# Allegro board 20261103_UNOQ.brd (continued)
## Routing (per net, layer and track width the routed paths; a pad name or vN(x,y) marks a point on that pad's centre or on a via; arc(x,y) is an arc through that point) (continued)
SM_LNBBCLK1: length 19.4
  TOP w0.05: 28.97,28.33 28.97,28.88 SOC1.U29
  TOP w0.066: R702.1 29.7,13.66 27.27,13.66 26.18,14.75 26.18,21.86 28.96,24.64 28.96,28.33 28.97,28.33
SM_RESIN_N: length 28.1
  TOP w0.066: R1201.1 23,24.67 22.93,24.6 22.93,20.41 22.45,19.93 22.45,18.9 23.95,17.4 23.95,15.34 24.4,14.89 v3(24.4,13.41)
  S3 w0.064: v3(24.4,13.41) 24.6,13.61 28.29,13.61 29.67,14.99 v3(30.05,14.99) 30.1,15.04 30.1,15.81 30.88,16.59 36.09,16.59 36.66,16.02 37.13,16.02 37.45,15.7 v3(37.85,15.7)
SM_RESIN_N_R: length 9.5
  TOP w0.066: SOC1.AJ20 24,32.48 23.67,32.81 22.84,32.81 22.46,32.43 22.46,27.85 23.34,26.97 23.34,26.4 C1201.1 R1201.2
SM_THERM: length 6.8
  S3 w0.064: v3(38.97,15.13) 38.97,15.33 39.08,15.43 39.49,15.43 40.16,14.76 40.16,14.41 40.05,14.3 40.05,14.13 41.96,12.22 v3(41.96,10.54)
SOC_BID0: length 2.8
  TOP w0.066: SOC1.AH3 23.97,39.28 23.51,39.74 22.87,39.74 R1316.1 R1315.2
SOC_BID1: length 2.5
  TOP w0.066: SOC1.AJ2 23.94,39.68 23.3,40.32 22.89,40.32 R1318.1 R1317.2
SOC_BT_UART_CTS: length 46.2
  TOP w0.064: v3(23.77,61.87) 23.75,61.85 20.84,61.85 20.3,61.31 11.51,61.31 10.2,60 7.61,60 7.27,60.34 4.71,60.34 R2906.1
  S3 w0.064: v3(23.77,61.87) 23.89,61.75 23.89,57.59 24.91,56.57 24.91,51.65 34.04,42.52 34.04,40.4
  S3 w0.066: 34.04,40.4 33.87,40.23 33.87,40.18 v3(33.77,40.08)
SOC_BT_UART_RTS: length 45.2
  TOP w0.066: v3(33.78,40.5) 33.57,40.5 33.37,40.3 33.37,40.08 SOC1.F1
  S3 w0.064: v3(4.12,63.34) 4.52,62.94 7.34,62.94 8.44,61.84 v4(8.44,60.12) ; 33.89,40.62 33.89,42.44 24.75,51.58 24.75,55.97 v4(24.28,56.44)
  S3 w0.066: 33.89,40.62 v3(33.78,40.5)
  V5 w0.064: v4(8.44,60.12) 9.67,58.89 10.14,58.89 12.31,56.72 21.57,56.72 22.46,55.83 23.67,55.83 v4(24.28,56.44)
SOC_BT_UART_RX: length 33.3
  TOP w0.064: v3(22.69,60.46) 22.71,60.48 24.38,60.48 25.02,61.11 25.02,61.95 24.42,62.55 R2901.1
  S3 w0.064: v3(32.51,40.02) 32.51,41.58 27.73,46.36 26.36,46.36 25.73,46.99 22.97,46.99 21.22,48.74 21.22,52.93 20.74,53.41 20.74,57.62 22.69,59.57 v3(22.69,60.46)
SOC_BT_UART_TX: length 24.4
  TOP w0.064: v3(24.11,55.3) 24.43,55.62 24.43,58.29 R2908.1 ; 32.97,40.35 32.97,40.08 SOC1.G1
  TOP w0.066: v3(33.12,41.26) 32.97,41.11 32.97,40.35
  S3 w0.064: v3(24.11,55.3) 24.52,54.89 24.52,49.48 26.43,47.57 27.36,47.57 31.09,43.84 31.09,43.69 33.12,41.66 v3(33.12,41.26)
SOC_CAM_MCLK0: length 29.4
  TOP w0.05: v3(31.3,39.58) 31.3,39.61 31.37,39.68
  TOP w0.066: v3(26.58,44.88) v3(26.58,56.42)
  S3 w0.05: 31.46,40.44 31.46,39.93 31.3,39.77 v3(31.3,39.58)
  S3 w0.064: v3(26.58,44.88) 27.92,44.88 31.46,41.34 31.46,40.44 ; v3(26.58,56.42) v4(26.58,64.25)
  S6 w0.064: v4(26.58,64.25) v1(26.93,64.25)
  BOTTOM w0.066: R2638.1 27.08,64.25 v1(26.93,64.25)
SOC_CAM_MCLK0_R: length 13.1
  BOTTOM w0.066: R2638.2 D26046.2 29.37,63.4 30.22,64.25 35.46,64.25 36.2,63.52 JMEDIA1.16
SOC_CAM_MCLK1: length 52
  TOP w0.066: SOC1.M2 31,39.68 31.26,39.95 31.26,41 30.49,41.77 22.14,41.77 v3(21.41,41.05) ; v3(22.9,49.03) 22.65,48.78 15.31,48.78 v3(15.04,48.51)
  S3 w0.064: v3(21.41,41.05) 21.41,41.18 20.17,42.42 18.43,42.42 15.5,45.35 15.5,47.52 15.04,47.98 v3(15.04,48.51) ; v4(24.31,63.81) 23.24,62.74 23.24,59.17 21.26,57.19 21.26,53.68 23.08,51.86 23.08,49.21 v3(22.9,49.03)
  S6 w0.064: v1(24.56,63.69) 24.43,63.69 v4(24.31,63.81)
  BOTTOM w0.066: R2639.1 27.87,62.89 27.14,63.62 24.63,63.62 v1(24.56,63.69)
SOC_CAM_MCLK1_R: length 13.2
  BOTTOM w0.066: R2639.2 D26047.2 29.2,62.89 30.31,64 35.34,64 35.94,63.4 35.94,60.4 34.92,59.38 34.92,58.85
SOC_GPIO18: length 91.6
  TOP w0.066: SOC1.M1 30.97,40.08 30.97,40.6 30.38,41.19 22.25,41.19 21.79,40.73 v3(21.79,40.44)
  S3 w0.064: v3(21.79,40.44) 21.06,40.44 v4(20.9,40.6)
  V5 w0.064: v4(0.97,41.78) 0.75,41.55 0.75,4.56 1.82,3.49 4.28,3.49 4.44,3.65 v4(5.58,3.65)
  S6 w0.064: v4(20.9,40.6) 20.89,40.61 20.75,40.61 v1(20.62,40.74) ; v4(5.58,3.65) 6.43,4.5 8.78,4.5 10.78,2.5 13.32,2.5 v1(13.48,2.67) ; v4(0.97,41.78) 1.18,41.99 v1(1.19,41.99)
  BOTTOM w0.066: v1(13.48,2.67) 14.81,3.99 D26075.2 14.81,7.87 JMISC1.49 ; v1(1.19,41.99) 7.82,41.99 10.34,39.47 10.77,39.47 11.66,38.58 14.04,38.58 15.83,40.37 18.55,40.37 18.88,40.7 20.58,40.7 v1(20.62,40.74)
SOC_GPIO28: length 96.7
  TOP w0.066: v3(13.95,47.35) 13.13,47.35 12.34,48.14 6.06,48.14 5.79,47.87 3.81,47.87 3.28,48.4 1.42,48.4 1.19,48.17 1.19,4.61 1.93,3.87 3.23,3.87 4.1,4.74 v6(4.42,4.74)
  S3 w0.05: 31.62,40.44 31.62,39.92 31.49,39.8 31.49,39.77 31.48,39.76 31.48,39.4 v3(30.97,38.88)
  S3 w0.064: 31.62,40.44 31.62,41.45 27.81,45.26 26.19,45.26 25.91,44.98 22.99,44.98 v4(22.05,45.92) ; v4(14.28,47.35) v3(13.95,47.35)
  S6 w0.064: v4(14.28,47.35) 14.41,47.35 15.57,46.19 17.57,46.19 18.22,45.54 21.66,45.54 v4(22.05,45.92)
  G7 w0.064: v1(13.15,5.33) 12.83,5.65 5.61,5.65 4.7,4.74 v6(4.42,4.74)
  BOTTOM w0.066: JMISC1.51 13.49,7.93 D26076.2 13.49,5.67 v1(13.15,5.33)
SOC_GPIO_0_SE0: length 39.5
  S3 w0.05: 29.15,28.33 29.31,28.49 ; 29.58,29.47 v3(29.37,29.68)
  S3 w0.064: 29.58,29.47 29.58,28.87 29.55,28.84 29.55,28.81 29.44,28.7 29.41,28.7 29.31,28.6 29.31,28.49 ; 29.15,28.33 26.77,25.95 23.18,25.95 22.28,25.04 18.4,25.04 16.69,23.33 16.69,17.17 15.46,15.95 v4(14.38,15.95)
  S6 w0.064: v4(14.38,15.95) 14.38,14.88 21.62,7.64 21.62,6.5 v1(21.67,6.45)
  BOTTOM w0.066: JMISC1.37 22.22,7 v1(21.67,6.45)
SOC_GPIO_1_SE0: length 39.4
  S3 w0.05: v3(29.37,29.28) 29.17,29.08 29.17,28.54 28.96,28.33 28.87,28.33
  S3 w0.064: v4(13.84,15.98) 14.15,16.28 15.57,16.28 16.53,17.25 16.53,23.44 18.29,25.2 22.21,25.2 23.11,26.1 26.63,26.1 28.87,28.33
  S6 w0.064: v1(20.73,6.46) 21.09,6.82 21.09,7.95 13.84,15.2 v4(13.84,15.98)
  BOTTOM w0.066: JMISC1.39 20.95,7.01 20.73,6.79 v1(20.73,6.46)
SOC_GPIO_2_SE0: length 40.5
  S3 w0.05: 28.61,28.33 28.79,28.51 28.79,29.5 v3(28.97,29.68)
  S3 w0.064: 28.61,28.33 26.53,26.25 23.01,26.25 22.13,25.37 18.2,25.37 16.35,23.52 16.35,17.3 15.49,16.43 13.77,16.43 v4(13.31,15.98)
  S6 w0.064: v1(19.84,6.46) 20.24,6.46 20.8,7.02 20.8,8.02 13.31,15.51 v4(13.31,15.98)
  BOTTOM w0.066: JMISC1.41 19.84,7.93 v1(19.84,6.46)
SOC_GPIO_3_SE0: length 40.2
  S3 w0.05: 28.19,28.33 28.39,28.53 28.39,29.5 v3(28.57,29.68)
  S3 w0.064: v4(12.85,16.43) 13.18,16.76 15.38,16.76 16.07,17.45 16.07,23.72 18.03,25.68 22.03,25.68 22.91,26.55 26.41,26.55 28.19,28.33
  S6 w0.064: v1(18.62,6.46) 18.62,6.98 19.44,7.8 19.44,9.16 12.85,15.75 v4(12.85,16.43)
  BOTTOM w0.066: JMISC1.43 18.41,6.67 v1(18.62,6.46)
SOC_GPIO_82_SE0: length 41.4
  S3 w0.05: 28.39,28.33 28.57,28.51 v3(28.57,29.28)
  S3 w0.064: 28.39,28.33 26.46,26.4 22.96,26.4 22.09,25.53 18.11,25.53 16.22,23.64 16.22,17.38 15.44,16.61 13.49,16.61 12.9,16.03 12.29,16.03 v4(12.22,15.95)
  S6 w0.064: v1(17.32,6.48) 17.32,6.62 18.34,7.64 18.34,9.12 12.32,15.14 12.32,15.85 v4(12.22,15.95)
  BOTTOM w0.066: JMISC1.47 16.06,7.9 D26074.2 17.28,6.44 v1(17.32,6.48)
SOC_GPIO_86_SE0: length 36.9
  TOP w0.05: 28.57,28.33 SOC1.V30
  TOP w0.066: v3(25.73,16.41) 25.73,17.53 25.77,17.57 25.77,22.18 28.57,24.97 28.57,28.33
  S3 w0.064: v3(25.73,16.41) 21.59,16.41 18.82,13.64 v4(14.36,13.64)
  S6 w0.064: v4(14.36,13.64) 14.48,13.64 18.48,9.64 18.48,7.56 17.71,6.79 v1(17.71,6.48)
  BOTTOM w0.066: v1(17.71,6.48) 17.71,6.94 17.14,7.5 JMISC1.45
SOC_GPIO_98: length 85.6
  TOP w0.066: v6(4.25,6.35) 4.17,6.43 1.81,6.43 1.34,6.9 1.34,38.99 1.64,39.29 3.24,39.29 3.61,38.92 v3(6.88,38.92)
  G2 w0.064: v3(25.39,30.88) 24.99,31.28 v2(24.97,31.28)
  S3 w0.064: v3(6.88,38.92) 6.88,38.55 8.73,36.7 10.2,36.7 13.6,33.29 19.11,33.29 22.31,30.09 24.6,30.09 v3(25.39,30.88)
  G7 w0.064: v1(17.63,10.91) 18.3,10.24 18.3,7.82 16.55,6.07 4.53,6.07 v6(4.25,6.35)
  BOTTOM w0.066: D26091.2 17.16,13.46 17.16,12 17.14,11.98 17.14,11.4 v1(17.63,10.91)
SOC_GPIO_99: length 78.9
  TOP w0.066: v6(4.22,6.91) 3.75,7.38 3.75,8.87 3.84,8.96 3.84,37.98 4.52,38.66 6.97,38.66 7.27,38.36 v3(7.49,38.36)
  G2 w0.064: v2(24.57,31.28) v3(24.57,30.84)
  S3 w0.064: v3(7.49,38.36) 7.49,38.15 8.8,36.85 10.26,36.85 13.66,33.44 19.17,33.44 22.37,30.24 24.07,30.24 24.57,30.74 v3(24.57,30.84)
  G7 w0.064: v1(17.3,10.83) 18.14,9.99 18.14,7.89 16.44,6.19 5.05,6.19 4.33,6.91 v6(4.22,6.91)
  BOTTOM w0.066: D26092.2 15.69,13.62 15.87,13.44 15.87,11.24 16.16,10.95 17.18,10.95 v1(17.3,10.83)
SOC_GPIO_100: length 77.4
  TOP w0.066: v3(7.84,38.12) 7.22,38.12 6.92,38.42 4.63,38.42 3.98,37.77 3.98,8.85 3.9,8.77 3.9,7.9 v6(4.25,7.55)
  G2 w0.064: v2(24.17,31.28) v3(24.17,30.85)
  S3 w0.064: v3(7.84,38.12) 8.92,37.04 10.29,37.04 13.73,33.6 19.21,33.6 22.43,30.38 23.98,30.38 24.17,30.57 v3(24.17,30.85)
  G7 w0.064: v1(16.94,10.65) 17.24,10.35 17.24,7.17 16.39,6.32 5.48,6.32 v6(4.25,7.55)
  BOTTOM w0.066: D26093.2 14.42,13.62 14.6,13.44 14.6,11.42 15.24,10.78 16.81,10.78 v1(16.94,10.65)
SOC_GPIO_101: length 79.6
  TOP w0.066: v6(4.24,8.27) 4.12,8.39 4.12,37.4 4.85,38.13 v3(6.86,38.13)
  G2 w0.064: v2(25.77,31.68) v3(25.77,31.3)
  S3 w0.064: v3(25.77,31.3) 25.77,30.87 24.82,29.92 22.24,29.92 19.04,33.12 13.53,33.12 10.22,36.43 8.56,36.43 v3(6.86,38.13)
  G7 w0.064: v6(4.24,8.27) 4.77,7.74 4.77,7.28 5.59,6.46 16.33,6.46 17.1,7.23 17.1,10.02 v1(16.86,10.26)
  BOTTOM w0.066: v1(16.86,10.26) 16.53,10.59 13.73,10.59 13.33,10.99 13.33,13.44 13.15,13.62 D26094.2
SOC_I2S_D0: length 29.6
  TOP w0.064: v3(21.22,35.88) 21.22,36 20.13,37.09 20.13,41.67 21.41,42.95 36.42,42.95 36.55,43.09
  S3 w0.064: v3(21.22,35.88) 21.25,35.85 21.6,35.85 22.6,34.85 22.6,32.09 22.79,31.9 23.01,31.9 23.22,31.68 v3(24.17,31.68)
SOC_I2S_D0_R: length 9.8
  G2 w0.064: v3(36.37,51.69) 36.37,51.74 v2(36.53,51.89)
  S3 w0.064: v3(36.37,51.69) 36.37,51.41 36.02,51.05 35.46,51.05 35.1,50.7 35.1,46.81 36.55,45.36 v3(36.55,43.6)
SOC_I2S_SCK: length 31.7
  TOP w0.064: v3(21.51,35.18) 21.32,35.37 21.32,35.67 21.43,35.78 21.43,35.99 20.31,37.11 20.31,41.6 21.49,42.78 37,42.78 R3016.1
  S3 w0.064: v3(25.37,31.68) 25.16,31.47 24.62,31.47 24.39,31.25 23.24,31.25 22.97,31.52 22.67,31.52 22.21,31.98 22.21,34.73 21.76,35.18 v3(21.51,35.18)
SOC_I2S_SCK_R: length 10.4
  S3 w0.064: v3(37,51.97) 36.58,51.54 36.58,51.16 36.25,50.83 35.61,50.83 35.27,50.48 35.27,46.87 36.71,45.43 36.71,43.85 v3(37.14,43.42)
SOC_I2S_WS: length 30.8
  TOP w0.064: R3017.1 37.6,42.6 21.56,42.6 20.48,41.52 20.48,37.19 21.61,36.06 21.61,35.65 v3(21.53,35.57)
  S3 w0.064: v3(24.57,31.68) 24.33,31.44 23.25,31.44 22.98,31.71 22.72,31.71 22.39,32.04 22.39,34.85 21.65,35.59 21.55,35.59 v3(21.53,35.57)
SOC_I2S_WS_R: length 10.3
  S3 w0.064: v3(37.79,43.3) 36.89,44.19 36.89,45.51 35.45,46.95 35.45,50.39 35.71,50.65 36.42,50.65 36.97,51.2 v3(36.97,51.54)
SOC_LED1_BLU: length 54.7
  TOP w0.066: v3(22.11,40.66) 22.39,40.93 24.57,40.93 25.77,39.73 SOC1.AE2 ; v3(19.06,41.66) 19.06,41.75 20.95,43.64 28.81,43.64 30.1,44.93 38.95,44.93 40.41,43.47 45.36,43.47 45.76,43.07 v3(46.84,43.07)
  S3 w0.064: v3(22.11,40.66) 21.25,40.66 20.25,41.66 v3(19.06,41.66) ; v4(46.78,43.36) 46.84,43.3 v3(46.84,43.07)
  S6 w0.064: v1(47.05,43.26) 46.95,43.36 v4(46.78,43.36)
  BOTTOM w0.066: v1(47.05,43.26) 47.05,43.26 48.68,41.63 48.68,35.1 47.96,34.38 41.58,34.38 R2714.1
SOC_LED1_BLU_B: length 1.5
  BOTTOM w0.066: Q2708.2 40.85,33.9 C2703.1 R2714.2
SOC_LED1_BLU_C: length 42.3
  BOTTOM w0.066: R2725.2 41.95,6.22 42.73,7 48.28,7 48.76,7.48 48.76,22.98 43.15,28.59 39.48,28.59 37.7,30.37 37.7,32.6 37.4,32.9 37.4,34.3 37.65,34.55 Q2708.6
SOC_LED1_BLU_D: length 3.8
  TOP w0.066: v3(41.91,4.44) 42,4.53 44.17,4.53 44.49,4.21 D27301.3
  S3 w0.064: v3(41.91,4.44) 41.79,4.44 v4(41.61,4.62)
  S6 w0.064: v1(41.95,4.85) 41.84,4.85 v4(41.61,4.62)
SOC_LED1_GRN: length 54.7
  TOP w0.066: v3(47.8,43.64) 47.7,43.54 45.73,43.54 45.49,43.78 40.54,43.78 39.08,45.24 29.97,45.24 28.68,43.95 20.74,43.95 18.69,41.9 18.69,39.3 v3(18.81,39.18)
  S3 w0.064: v3(47.8,43.64) 47.94,43.64 48.1,43.8 v4(48.1,43.82) ; v3(18.81,39.18) 18.89,39.1 24.02,39.1 24.2,39.28 v3(25.37,39.28)
  S6 w0.064: v4(48.1,43.82) v1(48.1,43.52)
  BOTTOM w0.066: v1(48.1,43.52) 48.08,43.5 48.08,43.29 49.26,42.11 49.26,34.86 48.2,33.8 46.05,33.8 R2713.1
SOC_LED1_GRN_B: length 3
  BOTTOM w0.066: Q2707.5 44.3,31.9 44.1,32.1 44.1,32.9 44.55,33.35 C2702.1 R2713.2
SOC_LED1_GRN_C: length 34.2
  BOTTOM w0.066: Q2707.3 43.65,32.55 43.9,32.3 43.9,31.04 44.27,30.67 46.83,30.67 49.34,28.16 49.34,7.21 48.41,6.28 45.8,6.28 45.64,6.12 R2724.2
SOC_LED1_GRN_D: length 2.6
  TOP w0.066: D27301.4 44.51,3.13 v3(44.51,3.52)
  S3 w0.064: v4(44.85,3.61) 44.76,3.52 v3(44.51,3.52)
  S6 w0.064: v4(44.85,3.61) v1(45.27,3.61)
  BOTTOM w0.066: v1(45.27,3.61) 45.64,3.98 R2724.1
SOC_LED1_RED: length 57
  TOP w0.066: v3(47.26,43.31) 45.75,43.31 45.43,43.63 40.48,43.63 39.02,45.09 30.03,45.09 28.74,43.8 20.8,43.8 18.84,41.84 18.84,39.54 v3(19.03,39.35)
  S3 w0.064: v3(19.03,39.35) 19.14,39.24 23.92,39.24 24.13,39.45 24.73,39.45 v3(24.97,39.68) ; v3(47.26,43.31) 47.61,43.31 v4(47.65,43.27)
  S6 w0.064: v4(47.65,43.27) 47.65,43.46 v1(47.81,43.62)
  BOTTOM w0.066: v1(47.81,43.62) 47.81,43.35 49.11,42.05 49.11,34.92 48.14,33.95 43.65,33.95 42.75,33.05 R2712.1
SOC_LED1_RED_B: length 1.5
  BOTTOM w0.066: R2712.2 C2701.1 43.05,31.95 Q2707.2
SOC_LED1_RED_C: length 30.4
  BOTTOM w0.066: R2723.2 48.16,5.82 49.49,7.15 49.49,28.3 46.95,30.84 45.83,30.84 45.41,31.25 Q2707.6
SOC_LED1_RED_D: length 3.3
  S3 w0.064: v4(46.3,4.44) 46.25,4.39 43.93,4.39 v3(43.64,4.1)
  S6 w0.064: v4(46.3,4.44) 46.56,4.7 v1(46.56,4.85)
SOC_LED2_BLU: length 60.3
  TOP w0.066: v3(18.23,38.88) 18.23,39.3 18.38,39.45 18.38,42.03 20.61,44.26 28.55,44.26 29.84,45.55 39.21,45.55 40.67,44.09 45.62,44.09 45.71,44 47.31,44 v3(47.58,44.27)
  S3 w0.064: v3(18.23,38.88) 18.34,38.77 24.46,38.77 v3(24.57,38.88) ; v3(47.58,44.27) 47.58,44.11 v4(47.69,44)
  S6 w0.064: v1(47.53,43.62) 47.53,43.76 47.69,43.92 v4(47.69,44)
  BOTTOM w0.066: R2717.1 41.6,33 42.69,34.09 48.08,34.09 48.97,34.98 48.97,41.92 47.53,43.36 v1(47.53,43.62)
SOC_LED2_BLU_B: length 2.8
  BOTTOM w0.066: Q2709.5 41.3,29.9 41,30.2 C2706.1 R2717.2
SOC_LED2_BLU_C: length 34.6
  BOTTOM w0.066: R2728.2 43.8,6.25 44.19,6.64 48.33,6.64 49.06,7.37 49.06,23.26 43.38,28.93 41.07,28.93 40.8,29.2 40.8,30.1 40.35,30.55 Q2709.3
SOC_LED2_BLU_D: length 3
  TOP w0.066: v3(42.22,3.88) 42.22,3.9 42.3,3.98 D27302.3
  S3 w0.064: v3(42.22,3.88) 42.03,3.7 v4(41.98,3.7)
  S6 w0.064: v1(42.25,3.89) 42.06,3.7 v4(41.98,3.7)
  BOTTOM w0.066: v1(42.25,3.89) 42.83,3.89 R2728.1
SOC_LED2_GRN: length 61.4
  TOP w0.066: v3(47.13,43.77) 45.74,43.77 45.56,43.95 40.61,43.95 39.15,45.41 29.9,45.41 28.61,44.12 20.67,44.12 18.52,41.97 18.52,39.09 v3(18.51,39.08)
  S3 w0.064: v3(18.51,39.08) 18.65,38.94 24.09,38.94 24.27,39.12 24.73,39.12 v3(24.97,38.88) ; v4(47.17,44.06) 47.13,44.02 v3(47.13,43.77)
  S6 w0.064: v4(47.17,44.06) 47.13,44.02 47.13,43.71 47.24,43.6 v1(47.24,43.56)
  BOTTOM w0.066: R2716.1 40.15,31.85 42.53,34.23 48.02,34.23 48.83,35.04 48.83,41.81 47.24,43.4 v1(47.24,43.56)
SOC_LED2_GRN_B: length 3.3
  BOTTOM w0.066: Q2709.2 38.9,29.9 38.5,30.3 C2705.1 R2716.2
SOC_LED2_GRN_C: length 31.2
  BOTTOM w0.066: R2727.2 44.72,6.1 45.09,6.47 48.36,6.47 49.2,7.31 49.2,23.43 43.53,29.09 41.96,29.09 Q2709.6
SOC_LED2_GRN_D: length 3.6
  TOP w0.066: D27302.4 42.59,3.26 v3(42.31,3.54)
  S3 w0.064: v3(42.31,3.54) 42.5,3.54 v4(42.62,3.66)
  S6 w0.064: v1(42.95,3.56) 42.85,3.66 v4(42.62,3.66)
  BOTTOM w0.066: R2727.1 43.43,3.56 v1(42.95,3.56)
SOC_LED2_RED: length 60.2
  TOP w0.066: v3(18.02,38.65) 18.02,39.32 18.24,39.54 18.24,42.09 20.55,44.41 28.49,44.41 29.78,45.7 39.27,45.7 40.73,44.24 v3(46.56,44.24)
  S3 w0.064: v4(46.7,43.96) 46.7,44.1 v3(46.56,44.24) ; v3(25.37,38.88) 25.11,38.62 18.05,38.62 v3(18.02,38.65)
  S6 w0.064: v4(46.7,43.96) 46.87,43.79 v1(46.87,43.72)
  BOTTOM w0.066: v1(46.87,43.72) 46.84,43.72 46.83,43.71 46.83,43.18 48.54,41.47 48.54,35.16 47.9,34.52 42.08,34.52 41.2,35.4 R2715.1
SOC_LED2_RED_B: length 3.1
  BOTTOM w0.066: R2715.2 C2704.1 39.05,34.05 38.9,33.9 Q2708.5
SOC_LED2_RED_C: length 41
  BOTTOM w0.066: Q2708.3 39.76,33.25 39.19,32.68 38.38,32.68 37.9,32.2 37.9,30.4 39.54,28.76 43.27,28.76 48.9,23.13 48.9,7.41 48.3,6.81 43.45,6.81 42.87,6.23 R2726.2
SOC_LED2_RED_D: length 2.7
  TOP w0.066: v1(41.58,3.8) 41.74,3.96 D27302.2
  S3 w0.064: v1(41.58,3.8) v4(41.21,3.8)
  S6 w0.064: v4(41.21,3.8) v1(41.58,3.8)
  BOTTOM w0.066: v1(41.58,3.8) 41.82,3.8 R2726.1
SOC_MCU_LPUART1_CTS: length 41.3
  S3 w0.064: v3(27.76,29.25) 27.79,29.25 27.79,29.24 27.96,29.07 27.96,28.57 26.24,26.85 22.78,26.85 21.94,26.01 17.82,26.01 15.78,23.97 15.78,17.57 15.26,17.05 7.71,17.05 v4(6.6,18.16)
  S6 w0.064: v1(6.54,27.24) 6.48,27.18 6.48,26.11 7.04,25.55 7.04,23.67 6.6,23.24 v4(6.6,18.16)
  BOTTOM w0.064: R2502.2 6.91,27.61 v1(6.54,27.24)
SOC_MCU_LPUART1_RTS: length 26
  S3 w0.064: v3(27.37,29.28) 27.16,29.08 27.16,28.73 25.88,27.45 22.46,27.45 21.95,26.95 19.3,26.95 17.55,28.7 7.51,28.7 v4(6.81,28)
  S6 w0.064: v1(6.62,25.34) 6.52,25.44 6.52,25.5 6.02,26 6.02,27.29 6.73,28 v4(6.81,28)
SOC_MCU_LPUART1_RX: length 42.1
  S3 w0.064: v4(19.74,27.44) 19.83,27.53 20.98,27.53 21.4,27.95 25.43,27.95 26.58,29.1 26.78,29.1 v3(26.97,29.28) ; v4(5.71,16.71) 6.15,16.28 11.35,16.28 12.04,15.6 18.19,15.6 18.85,16.26 v4(19.35,16.26)
  S6 w0.064: v1(6.63,24.36) 6.63,23.67 6.43,23.47 6.43,20.5 5.49,19.56 5.49,17.04 5.71,16.81 v4(5.71,16.71) ; v4(19.35,16.26) 19.94,16.84 19.94,27.29 19.78,27.44 v4(19.74,27.44)
SOC_MCU_LPUART1_TX: length 23
  S3 w0.05: 27.55,28.62 27.55,29.5 v3(27.37,29.68)
  S3 w0.064: v4(6.96,26.24) 14.07,26.24 14.17,26.34 21.8,26.34 22.61,27.15 26.08,27.15 27.55,28.62
  S6 w0.064: v1(6.96,26.52) v4(6.96,26.24)
SOC_UART_RX_SE4: length 61.8
  TOP w0.064: v3(42.54,42.93) 42.06,42.45 21.65,42.45 20.65,41.45 20.65,37.26 21.75,36.16 21.75,33.49 21.37,33.11 21.37,30.36 21.25,30.24 21.25,29.33 v3(21.58,29) ; JCTL1.6 42.6,50.08 42.63,50.05 ; 42.63,50.05 v3(42.63,49.3) ; 42.63,50.05 43.03,49.65 44.47,49.65 44.7,49.88 44.7,53.43 45.26,53.99 47.87,53.99 49.43,55.55 49.43,56.4 v6(50.12,57.09)
  S3 w0.064: v3(42.63,49.3) 42.63,47.24 43.34,46.53 43.34,43.73 v3(42.54,42.93) ; v3(21.58,29) 21.78,28.8 23.66,28.8 23.78,28.68 24.77,28.68 v3(24.97,28.48)
  BOTTOM w0.064: TP2616.1 50.03,57.09 v6(50.12,57.09)
SOC_UART_TX_SE4: length 64.3
  TOP w0.064: v6(50.17,56.04) 50.17,55.66 48.51,54 48.51,46.71 47.78,45.98 42.77,45.98 42.27,46.48 JCTL1.4 42.67,47.54 v3(43.58,46.63) ; v3(21.62,29.38) 21.41,29.59 21.41,30.17 21.53,30.29 21.53,33.04 21.91,33.42 21.91,36.23 20.82,37.32 20.82,41.39 21.67,42.24 42.88,42.24 43.42,42.78 v3(43.42,42.93)
  S3 w0.064: v3(43.42,42.93) 43.65,43.16 43.65,46.56 v3(43.58,46.63) ; v3(25.37,28.88) 24.76,28.88 24.47,29.17 21.83,29.17 v3(21.62,29.38)
  BOTTOM w0.064: TP2615.1 49.88,55.75 v6(50.17,56.04)
SPMI_CLK: length 24.4
  TOP w0.066: R1205.1 21.94,23.22 21.94,18.44 23.41,16.97 23.41,14.44 v3(23.7,14.15)
  S3 w0.064: v3(36.71,16.26) 36.71,16.5 36.43,16.78 30.67,16.78 27.94,14.05 23.8,14.05 v3(23.7,14.15)
SPMI_CLK_R: length 12.4
  TOP w0.066: SOC1.AH19 24.55,32.88 24.31,33.12 23.83,33.12 23.48,33.47 22.74,33.47 21.98,32.71 21.98,25.54 22.29,25.23 22.29,24.49 22.13,24.34 C1202.1 R1205.2
SPMI_DATA: length 22.2
  TOP w0.066: R1206.1 22.14,20.51 22.14,18.55 23.58,17.11 23.58,14.6 v3(23.72,14.46)
  S3 w0.064: v3(37.28,16.26) 37.13,16.26 36.47,16.92 30.56,16.92 27.86,14.22 23.96,14.22 v3(23.72,14.46)
SPMI_DATA_R: length 14.2
  TOP w0.066: SOC1.AJ19 23.81,32.88 23.4,33.29 22.82,33.29 22.16,32.63 22.16,25.62 22.47,25.31 22.47,23.22 22.11,22.86 22.11,22.23 C1203.1 R1206.2
SWR_RX_CLK: length 40.3
  TOP w0.066: v3(23.27,32.4) 23.33,32.34 23.33,28.11 24.38,27.06 24.38,23.98 23.58,23.18 23.58,20.04 v3(23.24,19.7) ; v3(27.53,20.27) 27.53,21.62 28.8,22.89 33.84,22.89 36.38,25.43 42.7,25.43 43.14,24.98 R502.2
  S3 w0.064: v3(23.27,32.4) 23.42,32.26 25.02,32.26 25.18,32.42 25.18,32.56 25.26,32.64 25.26,32.78 v3(25.37,32.88) ; v3(27.53,20.27) 27.51,20.25 26.36,20.25 25.94,19.83 23.37,19.83 v3(23.24,19.7)
SWR_RX_CLK_R: length 7
  S3 w0.064: v3(43.14,23.68) 43.14,23.67 42.82,23.67 42.67,23.52 42.67,20.65 41.86,19.84 40.85,19.84 40.81,19.8 40.81,19.8 39.98,18.97 39.98,18.96 v3(39.82,18.81)
SWR_RX_DATA0: length 44
  TOP w0.066: v3(23.38,18.99) 23,19.37 23,19.78 23.43,20.21 23.43,23.23 24.23,24.03 24.23,26.92 23.18,27.97 23.18,31.92 22.97,32.13 v3(22.88,32.13) ; R503.2 44.16,25.1 43.54,25.73 36.28,25.73 33.76,23.22 28.6,23.22 27.03,21.64 27.03,19.81 v3(27.08,19.76)
  S3 w0.05: v3(25.77,32.88) 25.57,32.69 25.57,32.12 25.38,31.93 23.78,31.93
  S3 w0.064: v3(22.88,32.13) 22.97,32.13 23.17,31.93 23.78,31.93 ; v3(23.38,18.99) 23.44,19.05 23.61,19.05 23.87,19.31 26.07,19.31 26.52,19.76 v3(27.08,19.76)
SWR_RX_DATA0_R: length 8.1
  S3 w0.064: v3(44.16,23.68) 43.82,23.34 43.13,23.34 43.03,23.24 43.03,20.6 41.96,19.53 41.11,19.53 v3(39.82,18.24)
SWR_RX_DATA1: length 41.1
  TOP w0.066: v3(27.28,20.07) 27.28,21.64 28.7,23.06 33.81,23.06 36.33,25.58 43.21,25.58 43.65,25.13 R501.2 ; v3(23.49,19.37) 23.72,19.6 23.72,23.12 24.52,23.92 24.52,27.12 23.49,28.15 23.49,32.37 v3(23.62,32.5)
  S3 w0.064: v3(25.37,33.28) 25.15,33.06 25.15,32.77 25.04,32.66 23.78,32.66 v3(23.62,32.5) ; v3(27.28,20.07) 26.45,20.07 25.99,19.61 23.73,19.61 v3(23.49,19.37)
SWR_RX_DATA1_R: length 8.7
  S3 w0.064: v3(43.64,23.68) 43.43,23.47 42.93,23.47 42.85,23.39 42.85,20.6 41.94,19.68 40.98,19.68 39.57,18.28 39.57,17.99 v3(39.26,17.68)
SWR_TX_CLK: length 44
  TOP w0.066: v3(44.81,24.16) 44.75,24.21 44.75,25.22 43.92,26.06 36.21,26.06 33.72,23.57 28.45,23.57 26.62,21.74 26.62,19.2 v3(26.69,19.13) ; R1301.2 23.51,23.9 23.11,23.5 23.11,20.37 22.6,19.86 22.6,19.01 23.3,18.31 v3(23.82,18.31)
  S3 w0.064: v3(44.81,24.16) 44.7,24.16 44.51,23.96 44.51,23.54 43.89,22.92 43.89,20.84 43.35,20.29 43.09,20.29 42.08,19.29 42.08,19.29 42.04,19.25 41.16,19.25 40.13,18.23 40.13,18.17 ; v3(26.69,19.13) 26.36,18.8 24.15,18.8 23.82,18.47 v3(23.82,18.31)
  S3 w0.066: v3(40.13,17.96) 40.13,18.17
SWR_TX_CLK_R: length 10.6
  TOP w0.066: v3(23.01,32.51) 22.89,32.51 22.64,32.26 22.64,27.91 23.51,27.04 R1301.1
  S3 w0.05: 23.78,32.1 25.21,32.1 25.37,32.26 v3(25.37,32.48)
  S3 w0.064: 23.78,32.1 23.21,32.1 23.01,32.3 v3(23.01,32.51)
SWR_TX_DATA0: length 44
  TOP w0.066: v3(26.87,19.46) 26.8,19.53 26.8,21.67 28.52,23.39 33.74,23.39 36.24,25.9 43.75,25.9 44.5,25.15 v3(44.5,24.31) ; R1302.2 23.85,23.97 23.27,23.39 23.27,20.26 22.82,19.81 22.82,19.14 v3(23.39,18.57)
  S3 w0.064: v3(39.82,17.68) 39.82,17.95 40,18.14 40,18.17 40.01,18.17 40.01,18.26 41.15,19.41 42.04,19.41 43.21,20.57 43.2,20.58 43.2,20.78 43.31,20.88 43.44,20.88 43.69,21.13 43.69,22.88 44.4,23.59 44.4,24.23 44.48,24.31 v3(44.5,24.31) ; v3(23.39,18.57) 23.46,18.64 23.58,18.64 23.99,19.05 26.14,19.05 26.55,19.46 v3(26.87,19.46)
SWR_TX_DATA0_R: length 8.9
  TOP w0.066: R1302.1 23.85,27.01 22.93,27.93 v3(22.93,31.21)
  S3 w0.05: v3(25.77,32.48) 25.77,31.7 25.57,31.5
  S3 w0.064: v3(22.93,31.21) 23.04,31.1 25.17,31.1 25.57,31.5
TP_GPIO_72: length 2.4
  TOP w0.066: TP1311.1 23.52,33.93 24.17,33.28 SOC1.AH18
TP_GPIO_74: length 1.6
  TOP w0.066: TP1313.1 23.3,34.55 SOC1.AJ17
TP_GPIO_75: length 2.1
  TOP w0.066: TP1314.1 22.76,35 23.25,35 SOC1.AJ16
TP_GPIO_79: length 2.3
  TOP w0.066: SOC1.AH14 24.57,34.87 24.3,34.6 24.08,34.6 23.23,35.45 23.23,35.62 TP1310.1
TP_JTAG_SRST_N: length 51.4
  S3 w0.05: v3(26.17,29.28) 26.17,28.97 25.53,28.33
  S3 w0.064: v4(19.84,27.86) 21.03,27.86 21.27,28.1 25.29,28.1 25.53,28.33 ; v4(10.72,15.39) 11.35,14.76 17.88,14.76 v4(18.21,15.09)
  S6 w0.064: v1(17.61,4.27) 17.61,4.42 16.58,5.45 16.58,7.94 11.66,12.86 11.66,14.45 v4(10.72,15.39) ; v4(18.21,15.09) 18.21,15.27 18.82,15.88 19.53,15.88 19.74,16.08 19.74,16.38 20.09,16.74 20.09,27.8 20.03,27.86 v4(19.84,27.86)
  BOTTOM w0.066: TP1207.1 11.26,2.75 12.96,2.75 13.29,2.42 13.63,2.42 15.64,4.43 17.45,4.43 v1(17.61,4.27)
TP_JTAG_TCK: length 44.9
  TOP w0.066: v3(25.05,17.07) 25.05,17.32 24.84,17.53 24.84,23 25.93,24.09 25.93,27.99 26.17,28.23 26.17,28.48
  S3 w0.066: v4(11.18,14.15) 11.43,14.4 18.78,14.4 21.45,17.07 v3(25.05,17.07)
  S6 w0.064: v4(11.18,14.15) 11.18,12.9 16.27,7.81 16.27,5 17.07,4.21 v1(17.16,4.21)
  BOTTOM w0.066: v1(17.16,4.21) 15.76,4.21 13.72,2.17 TP1208.1
TP_JTAG_TDI: length 45.2
  TOP w0.066: v3(24.7,17.33) 24.61,17.42 24.61,23.09 25.77,24.25 SOC1.AE30
  S3 w0.064: v4(10.52,14.83) 10.79,14.55 18.64,14.55 19.43,15.34
  S3 w0.066: v3(24.7,17.33) 24.64,17.39 21.48,17.39 19.43,15.34
  S6 w0.064: v5(17.41,4.05) 17.41,4.31 16.43,5.29 16.43,7.86 11.5,12.79 11.5,14.36 11.03,14.83 v4(10.52,14.83)
  G7 w0.064: v5(17.41,4.05) 17.36,4.05 17.05,3.74 17.05,2.78 16.41,2.14 v1(15.18,2.14)
  BOTTOM w0.066: v1(15.18,2.14) 14.7,2.14 TP1209.1
TP_JTAG_TDO: length 44
  TOP w0.066: v3(25.3,16.89) 25.3,17.3 25,17.6 25,22.79 26.1,23.89 26.1,27.92 26.42,28.25 26.42,28.63 26.17,28.88
  S3 w0.064: v3(25.3,16.89) 21.51,16.89 18.85,14.22 11.81,14.22 11.35,13.77 v4(10.77,13.77)
  S6 w0.064: v4(10.77,13.77) 10.77,13.01 16.14,7.64 16.14,4.88 17.24,3.78 17.33,3.78 v5(17.36,3.75)
  G7 w0.064: v5(17.36,3.75) 17.36,2.31 v1(17.55,2.12)
  BOTTOM w0.066: TP1210.1 17.5,2.17 v1(17.55,2.12)
TP_JTAG_TMS: length 47.9
  S3 w0.064: v4(17.58,15.09) 11.73,15.09 11.07,15.75 v4(10.24,15.75) ; v4(19.45,28.88) 20.67,28.88 21.42,29.63 21.76,29.63 22.04,29.35 24.61,29.35 24.9,29.06 25.19,29.06 25.24,29.11 25.54,29.11 v3(25.77,28.88)
  S6 w0.064: v4(17.58,15.09) 17.73,15.09 19.79,17.14 19.79,26.85 19.26,27.37 19.26,28.69 v4(19.45,28.88) ; v4(10.24,15.75) 10.75,15.75 11.82,14.68 11.82,12.94 16.75,8.01 16.75,5.51 17.81,4.45 17.81,3.96 v5(17.79,3.94)
  G7 w0.064: v1(19.22,2.13) 19.22,2.26 17.79,3.69 v5(17.79,3.94)
  BOTTOM w0.066: TP1211.1 18.7,2.14 19.21,2.14 v1(19.22,2.13)
TP_JTAG_TRST_N: length 46.7
  TOP w0.066: SOC1.AC29 26.57,28.71 26.57,28.71 26.57,27.01 R1208.1 26.27,26.71 26.27,23.7 25.18,22.61 25.18,17.72 25.51,17.39 v3(25.51,16.69)
  S3 w0.066: v4(10.24,13.56) 10.39,13.41 11.28,13.41 11.84,13.97 18.85,13.97 21.5,16.62 25.44,16.62 v3(25.51,16.69)
  S6 w0.064: v5(18.1,3.68) 17.76,3.68 17.54,3.46 17.33,3.46 15.99,4.8 15.99,7.58 10.24,13.33 v4(10.24,13.56)
  G7 w0.064: v1(20.67,2.14) 19.64,2.14 v5(18.1,3.68)
TP_USB0_SS_RX1_M: length 4.3
  S3 w0.051: v3(32.97,28.88) 32.77,28.69 32.77,25.45 32.44,25.12 32.32,25.12 32.27,25.07 v3(32.27,24.9)
TP_USB0_SS_RX1_P: length 4.2
  S3 w0.051: v3(32.57,28.88) 32.65,28.8 32.65,25.5 32.39,25.25 32.24,25.25 32.2,25.29 32.2,25.4 v3(32.27,25.47)
TP_USB0_SS_TX1_M: length 5.4
  S3 w0.051: v3(32.17,29.28) 32.16,29.28 32.1,29.34 32.1,29.41 32.18,29.49 32.29,29.49 32.41,29.37 32.41,29.16 32.27,29.02 32.27,28.32 32.27,26.16 31.83,25.72 31.83,25.37 31.67,25.21 31.53,25.21 31.44,25.3 v3(31.44,25.44)
TP_USB0_SS_TX1_P: length 5.6
  S3 w0.051: v3(31.41,24.9) 31.41,24.96 31.54,25.09 31.72,25.09 31.95,25.32 31.95,25.67 32.39,26.11 32.39,28.35 32.38,28.35 32.38,28.97 32.52,29.11 32.52,29.42 32.34,29.6 32.24,29.6 v3(32.17,29.68)
USB0_HS_DM: length 96.9
  TOP w0.053: v6(37.8,66.66) 37.6,66.47 37.6,65.84 38.04,65.4 38.04,63.27 38.09,63.21 38.17,63.21 38.22,63.16 JUSB1.B7 38.22,62.02 38.07,61.87 37.57,61.87 37.47,61.78 JUSB1.A7 37.47,60.9 37.65,60.72 37.65,60.52 38.2,59.97 39.27,59.97 39.53,59.72 40.72,59.72 40.82,59.62 40.82,59.49 40.64,59.31 v3(40.64,59.18)
  S3 w0.051: v4(17.38,16.74) 17.56,16.92 17.56,17.56 17.69,17.69 17.69,18.27 18.62,19.2 19.77,19.2 24.6,24.02 27.94,24.02 28.95,25.04 30.49,25.04 31.86,26.41 31.86,28.62 32.02,28.78 32.02,28.89 31.97,28.94 31.82,28.94 v3(31.77,28.88) ; v3(40.64,59.18) 40.66,59.16 v4(40.66,58.9)
  S6 w0.051: v4(40.66,58.9) 40.85,58.72 40.85,57.78 40.31,57.24 34.82,57.24 30.74,53.16 30.74,48.42 30.29,47.98 28.17,47.98 27.37,47.17 24.4,47.17 21.63,44.4 18.25,44.4 15.02,41.18 15.02,23.19 15.88,22.33 15.88,18.87 16.95,17.79 16.95,17.72 16.91,17.68 16.91,17.6 16.98,17.53 17.05,17.53 17.1,17.58 17.17,17.58 17.53,17.22 17.53,16.89 v4(17.38,16.74)
  BOTTOM w0.053: v6(37.8,66.66) 38.19,67.05 TP2613.1
USB0_HS_DP: length 96.6
  TOP w0.053: v6(37.26,66.66) 37.46,66.47 37.46,65.78 37.9,65.34 37.9,63.27 37.85,63.21 37.77,63.21 37.72,63.16 v3(37.72,62.53) ; v3(41.14,59.18) 41.14,59.32 40.96,59.5 40.96,59.68 40.78,59.86 39.59,59.86 39.33,60.11 38.26,60.11 37.79,60.58 37.79,60.7 37.97,60.88 v3(37.97,61.23)
  S3 w0.051: v3(31.77,29.28) 31.91,29.14 32.03,29.14 32.14,29.02 32.14,28.73 31.98,28.57 31.98,26.34 30.56,24.92 29,24.92 27.99,23.9 24.65,23.9 19.83,19.08 18.67,19.08 17.81,18.22 17.81,17.64 17.68,17.51 17.68,16.91 v4(17.85,16.74) ; v3(37.97,61.23) 37.97,61.8 37.72,62.05 v3(37.72,62.53) ; v4(41.14,58.9) v3(41.14,59.18)
  S6 w0.051: v4(41.14,58.9) 40.97,58.73 40.97,57.73 40.36,57.12 34.87,57.12 30.86,53.11 30.86,48.37 30.34,47.85 28.22,47.85 27.42,47.05 24.45,47.05 21.68,44.28 18.3,44.28 15.14,41.12 15.14,23.24 16,22.38 16,18.92 17.65,17.27 17.65,16.95 17.85,16.75 v4(17.85,16.74)
  BOTTOM w0.053: v6(37.26,66.66) 37.26,66.69 36.9,67.05 TP2612.1
USB0_HS_REXT: length 2
  TOP w0.05: SOC1.K30 31.77,28.33
  TOP w0.066: R1203.1 31.33,27.32 31.77,27.76 31.77,28.33
USB0_SS_REXT: length 1.9
  TOP w0.05: SOC1.J30 32.17,28.33
  TOP w0.066: 32.17,28.33 32.17,27.69 31.84,27.36 R1202.1
USB0_SS_RX0_M: length 78
  TOP w0.053: U3001.B1 34.44,53.67 34.1,53.67 33.95,53.83 33.95,54.42 v3(33.84,54.53)
  S3 w0.051: v3(33.84,54.53) 33.74,54.43 v4(33.74,54.25) ; v3(33.37,28.48) 33.23,28.35 33.23,25.27 32.45,24.49 29.16,24.49 28.23,23.55 24.85,23.55 19.64,18.34 19.22,18.34 v4(19.05,18.17)
  S6 w0.051: v4(19.05,18.17) 18.9,18.32 18.34,18.32 16.75,19.91 16.75,22.74 15.91,23.57 15.91,40.84 18.64,43.58 22.26,43.58 25.05,46.37 28.01,46.37 28.78,47.14 29.46,47.14 29.59,47.02 29.59,46.66 29.64,46.61 29.84,46.61 29.89,46.66 29.89,47.02 30.01,47.14 30.32,47.14 30.44,47.02 30.44,46.66 30.49,46.61 30.69,46.61 30.74,46.66 30.74,47.02 30.87,47.14 31.37,47.14 31.73,47.5 31.73,49.7 31.85,49.82 32.23,49.82 32.28,49.87 32.28,50.08 32.23,50.13 31.85,50.13 31.73,50.25 31.73,50.55 31.85,50.68 32.23,50.68 32.28,50.73 32.28,50.93 32.23,50.98 31.85,50.98 31.73,51.1 31.73,51.41 31.85,51.53 32.23,51.53 32.28,51.58 32.28,51.78 32.23,51.84 31.85,51.84 31.73,51.96 31.73,52.46 32.44,53.17 33.79,53.17 33.94,53.32 33.94,54.05 v4(33.74,54.25)
USB0_SS_RX0_P: length 78.1
  TOP w0.053: v3(34.16,54.53) 34.09,54.46 34.09,53.89 34.16,53.81 34.44,53.81 U3001.A1
  S3 w0.051: v3(32.97,28.48) 33.11,28.34 33.11,25.32 32.4,24.61 29.11,24.61 28.18,23.67 24.8,23.67 19.59,18.46 19.24,18.46 v4(19.05,18.65) ; v4(34.21,54.25) 34.21,54.48 v3(34.16,54.53)
  S6 w0.051: v4(19.05,18.65) 18.84,18.44 18.39,18.44 18.24,18.59 18.24,18.67 18.3,18.72 18.3,18.8 18.22,18.88 18.13,18.88 18.08,18.83 18,18.83 17.92,18.91 17.92,19 17.97,19.05 17.97,19.13 17.89,19.21 17.81,19.21 17.75,19.16 17.67,19.16 17.59,19.24 17.59,19.32 17.64,19.38 17.64,19.46 17.56,19.54 17.48,19.54 17.42,19.49 17.34,19.49 16.87,19.96 16.87,22.79 16.03,23.62 16.03,40.79 18.69,43.46 22.31,43.46 25.1,46.25 28.06,46.25 28.83,47.02 29.41,47.02 29.46,46.97 29.46,46.61 29.59,46.49 29.89,46.49 30.01,46.61 30.01,46.97 30.06,47.02 30.27,47.02 30.32,46.97 30.32,46.61 30.44,46.49 30.74,46.49 30.87,46.61 30.87,46.97 30.92,47.02 31.42,47.02 31.85,47.45 31.85,49.65 31.9,49.7 32.28,49.7 32.4,49.82 32.4,50.13 32.28,50.25 31.9,50.25 31.85,50.3 31.85,50.5 31.9,50.55 32.28,50.55 32.4,50.68 32.4,50.98 32.28,51.1 31.9,51.1 31.85,51.15 31.85,51.36 31.9,51.41 32.28,51.41 32.4,51.53 32.4,51.83 32.28,51.96 31.9,51.96 31.85,52.01 31.85,52.41 32.49,53.05 33.84,53.05 34.06,53.27 34.06,54.1 v4(34.21,54.25)
USB0_SS_TX0_M: length 81.4
  TOP w0.053: v3(37.28,54.93) 37.38,54.83 37.38,54.69 37.1,54.41 37.1,54.07 U3001.A7
  S3 w0.051: v3(32.57,29.68) 32.62,29.68 32.7,29.6 32.7,29.45 33.6,28.56 33.6,28.38 33.48,28.26 33.48,25.2 32.46,24.18 29.29,24.18 28.39,23.27 24.97,23.27 19.39,17.69 18.53,17.69 v4(18.35,17.88) ; v3(37.28,54.93) 37.28,55.13 v4(37.19,55.22)
  S6 w0.051: v4(37.19,55.22) 37.39,55.42 37.39,55.63 37.29,55.73 36.83,55.73 36.64,55.54 34.07,55.54 31.41,52.87 31.41,48.26 30.6,47.45 28.43,47.45 27.64,46.66 24.82,46.66 22.02,43.86 18.48,43.86 15.6,40.97 15.6,23.42 16.46,22.56 16.46,19.14 16.85,18.75 16.93,18.75 16.98,18.8 17.06,18.8 17.15,18.71 17.15,18.63 17.1,18.58 17.1,18.5 17.18,18.42 17.26,18.42 17.31,18.47 17.39,18.47 17.47,18.39 17.47,18.3 17.43,18.26 17.43,18.17 17.51,18.09 17.59,18.09 17.64,18.14 17.72,18.14 17.8,18.06 17.8,17.98 17.75,17.93 17.75,17.85 17.9,17.7 18.17,17.7 v4(18.35,17.88)
USB0_SS_TX0_P: length 81.5
  TOP w0.053: U3001.A8 37.24,54.07 37.24,54.36 37.52,54.63 37.52,54.84 v3(37.61,54.93)
  S3 w0.051: v4(18.35,17.4) 18.52,17.57 19.44,17.57 25.02,23.15 28.44,23.15 29.34,24.05 32.51,24.05 33.6,25.15 33.6,28.21 33.72,28.33 33.72,28.61 32.82,29.5 32.82,29.6 32.9,29.68 v3(32.97,29.68) ; v4(37.67,55.22) 37.61,55.16 v3(37.61,54.93)
  S6 w0.051: v4(18.35,17.4) 18.17,17.58 17.85,17.58 16.34,19.09 16.34,22.5 15.47,23.37 15.47,41.02 18.43,43.98 21.97,43.98 24.77,46.78 27.58,46.78 28.37,47.57 30.55,47.57 31.29,48.31 31.29,52.92 34.02,55.66 36.59,55.66 36.78,55.85 37.34,55.85 37.51,55.68 37.51,55.38 v4(37.67,55.22)
USB_CC1: length 3.9
  TOP w0.066: v3(37.31,59.96) 37.23,59.96 U2602.7
  TOP w0.254: 37.23,59.96 U2602.4 37.23,58.35 R3005.2
  S3 w0.2: 38.39,60.85 38.4,60.86 v3(38.44,60.86)
  S3 w0.254: v3(37.31,59.96) 38.21,60.85 38.39,60.85
USB_CC1_R_MUX: length 10.4
  TOP w0.254: v3(37.56,57.51) 37.58,57.5 TP3004.1 ; v3(34.01,52.43) 34.09,52.34 U3001.E1
  S3 w0.254: v3(34.01,52.43) 34.01,52.93 33.38,53.56 33.38,55.17 34.12,55.91 34.12,57.1 34.95,57.94 36.91,57.94 37.34,57.51 v3(37.56,57.51)
USB_CC2: length 5.6
  TOP w0.254: U2602.6 U2602.5 38.23,58.9 R3006.2
  S3 w0.254: v3(37.25,62.16) 37.25,61.88 37.55,61.59 37.55,60.67 36.88,60.01 36.88,59.73 37.09,59.52 37.69,59.52 v3(37.73,59.55)
USB_CC2_R_MUX: length 13.3
  TOP w0.254: U3001.F1 33.99,51.94 33.87,52.07 v3(33.83,52.07) ; TP3005.1 39.02,58.59 v3(39.02,59.19)
  S3 w0.254: v3(33.83,52.07) 33.71,52.2 33.71,52.78 33.01,53.48 33.01,55.24 33.77,55.99 33.77,57.27 34.77,58.27 36.91,58.27 37.24,58.61 38.45,58.61 v3(39.02,59.19)
USB_I2C_SCL: length 36.5
  TOP w0.066: R3014.1 34.41,43.77 R3027.2 33.74,43.7 33.33,43.29 21.12,43.29 19.5,41.67 19.5,37.49 20.96,36.03 20.96,35.53 21.07,35.42 21.07,29.1 21.54,28.63 v3(21.54,27.72)
  S3 w0.064: v3(21.54,27.72) 21.62,27.8 25.5,27.8 26.58,28.88 26.82,28.88 v3(26.9,28.96)
USB_I2C_SDA: length 34.9
  TOP w0.066: v3(21.52,27.43) 21.33,27.62 21.33,28.59 20.92,29 20.92,35.29 20.81,35.4 20.81,35.96 19.31,37.46 19.31,41.75 21.01,43.44 31.29,43.44 31.49,43.64 R3015.1 32.03,43.78 R3026.2 ; SOC1.AB30 26.97,28.48 26.83,28.62 v3(26.78,28.62)
  S3 w0.064: v3(21.52,27.43) 21.75,27.65 25.57,27.65 26.42,28.5 26.65,28.5 v3(26.78,28.62)
USB_IN_MID: length 9.8
  TOP w0.15: 41.27,12.66 40.69,13.24 40.69,13.59 40.68,13.6 40.68,13.83 40.69,13.84 40.69,13.98 PMIC1.V24
  TOP w0.2: C608.1 41.27,12.66
  S3 w0.064: v3(40.71,13.93) 40.9,13.74 v4(40.96,13.74)
  S3 w0.2: v3(37.28,16.83) 37.03,17.07 37.03,17.06 v4(37.02,17.06)
  V5 w0.2: v4(38.71,16.13) 37.98,16.13 37.03,17.07 37.03,17.06 v4(37.02,17.06)
  S6 w0.064: v1(37.26,16.89) 37.19,16.97 37.12,16.97 v4(37.02,17.06)
  S6 w0.2: v4(38.71,16.13) 39.88,16.13 40,16.01 40,14 40.26,13.74 v4(40.96,13.74)
USB_PHY_PS: length 28.2
  TOP w0.066: R1319.2 R1320.1 24.39,16.34 v3(24.39,18.1) 24.39,23.07 25.03,23.71 25.03,27.25 23.93,28.35 23.93,28.64 SOC1.AJ29 ; v3(26.63,18.59) 27.76,19.72 27.76,21.59 28.91,22.73 35,22.73 R902.2
  S3 w0.064: v3(24.39,18.1) 24.82,18.53 26.57,18.53 v3(26.63,18.59)
USB_VBUS_IN: length 100.1
  TOP w0.2: PMIC1.V22 PMIC1.W23 40.41,13.69 40.41,13.26 40.08,12.93 R601.1 C602.1 C603.1 40.08,10.33 C601.1
  TOP w0.203: v3(40.24,14.21) 40.27,14.21 40.27,14.16 40.23,14.16 40.23,14.12 PMIC1.V22
  S3 w0.1: v3(44.32,16.01) 43.47,15.16 40.73,15.16 40.63,15.06 40.44,15.06 40.31,14.93 40.31,14.45 v4(40.51,14.25)
  S3 w0.203: v3(40.24,14.21) 40.47,14.21 v4(40.51,14.25)
  S3 w0.4: v4(38.78,41.58) 37.84,41.58 34.75,44.67 34.75,48.7 33.92,49.52 32.65,49.52 31.88,50.29 29.93,50.29 29.52,50.7 29.52,51.35 29.42,51.46 30.73,51.46 v3(31.04,51.16) ; v4(13.56,53.58) 13.37,53.39 v4(13.37,49.49)
  S3 w0.5: 29.42,51.46 28.06,51.46 v4(27.83,51.69)
  V5 w0.4: v4(27.83,51.69) 27.83,52.53 27.33,53.03 25.63,53.03 24.39,51.78 21.23,51.78 19.44,53.58 v4(13.56,53.58)
  S6 w0.5: v5(38.99,41.4) 38.84,41.55 38.81,41.55 38.81,41.58 v4(38.78,41.58) ; v1(13.88,49.63) 13.51,49.63 v4(13.37,49.49)
  G7 w0.4: v5(41.1,14.25) 41.84,14.25 42.53,14.95 46.06,14.95 47.07,13.94 48.86,13.94 49.19,14.27 49.19,20.02 48.21,21 48.21,32.36 49.22,33.37 49.22,41.88 48.49,42.61 41.56,42.61 40.7,41.75 39.34,41.75 v5(38.99,41.4)
  BOTTOM w0.5: v1(13.88,49.63) 14.11,49.86 Q2801.3
  vias: v1(14.05,49.76) v5(14.05,49.76) v5(39.14,41.26) v5(40.89,14.25)
VCOIN: length 77.6
  TOP w0.2: C709.1 C710.1 C712.1 v3(44.19,20.89) C711.1 C708.1
  TOP w0.203: v3(38.48,16.81) 38.47,16.83 PMIC1.H16
  S3 w0.203: v3(44.19,20.89) 44.19,20.79 v4(44.33,20.65) ; v3(38.48,16.81) 38.46,16.79 v4(38.46,16.54)
  V5 w0.203: v4(38.46,16.54) 38.53,16.61 39.24,16.61 40.87,18.24 40.87,20.7 41.61,21.44 44.02,21.44 44.15,21.31 44.15,20.84 v4(44.33,20.65)
  S6 w0.203: v1(18.39,14.53) 18.39,13.62 22.5,9.51 22.62,9.51 24.11,8.02 35.62,8.02 35.98,8.38 38.86,8.38 40.04,9.56 40.04,11.76 38.95,12.85 38.93,12.85 38.74,13.04 38.74,13.06 38.24,13.56 38.24,16.32 v4(38.46,16.54)
  BOTTOM w0.254: 18.12,14.8 17.83,15.09 17.83,15.52 17.88,15.57 17.88,18.49 16.02,20.35 C2524.1 C2526.1 14.5,21.01 14.45,21.01 13.9,21.56 MCU1.C1
  BOTTOM w0.381: 7.16,7.32 7.16,10.22 6.49,10.89 6.49,14.35 6.94,14.8 18.12,14.8 v1(18.39,14.53)
VCONN_IN: length 3.1
  G2 w0.203: v3(34.87,51.59) 34.87,51.66 34.95,51.74 v2(34.95,51.92)
  S3 w0.203: v3(34.87,51.59) v4(34.87,51.31) ; v3(33.27,50.16) v4(33.07,50.37)
  S6 w0.203: v4(33.07,50.37) 34.01,51.31 v4(34.87,51.31)
VFB_NEG_S3: length 6.2
  S3 w0.058: 30.91,19.52 31.1,19.53 31.29,19.74 31.39,19.74 31.44,19.68 31.44,18.61 31.88,18.17 35.24,18.17 35.29,18.12 35.45,17.97 v3(35.7,17.97)
VFB_NEG_S4: length 5.5
  S3 w0.058: v3(35.27,17.7) 35.27,17.93 35.16,18.04 30.54,18.04 30.45,18.13 30.13,18.13
VFB_S3: length 5.9
  S3 w0.058: 30.89,20.04 31.02,20.05 31.21,19.87 31.44,19.87 31.57,19.74 31.57,18.66 31.93,18.3 35.37,18.3 v3(35.42,18.25)
VFB_S4: length 5
  S3 w0.058: 30.13,17.62 30.41,17.62 30.7,17.91 34.94,17.91 v3(35,17.85)
VOLUME_DOWN_N: length 26.2
  TOP w0.066: v3(43.02,46.21) 43.52,46.21 44.2,46.89 v6(44.2,47.35) 44.4,47.54 JCTL1.3 47.52,47.54 48.37,48.39 48.37,54.06 49.74,55.43 49.74,56.23 49.9,56.39 51.27,56.39 v6(51.93,57.05) ; v3(41.77,42.95) 41.51,42.69 38.97,42.69 R708.1 38.32,42.8 R1321.2
  S3 w0.064: v3(43.02,46.21) 43.02,44.2 v3(41.77,42.95)
  BOTTOM w0.066: v6(51.93,57.05) 51.93,57.32 TP2618.1 ; v6(44.2,47.35) 44.67,47.35 D26001.2
VOLUME_DOWN_R: length 28.5
  TOP w0.066: v3(19.8,40.32) 19.8,41.62 21.29,43.11 35.45,43.11 36.25,43.91 37.83,43.91 38.31,43.43 R1321.1
  S3 w0.064: v3(19.8,40.32) 19.8,39.7 19.95,39.55 23.8,39.55 24.26,40.01 25.88,40.01 26.17,39.72 v3(26.17,39.68)
VOLUME_UP_N: length 64
  TOP w0.066: 45.9,50.08 JCTL1.5 ; 45.9,50.08 45.27,50.08 44.87,50.48 44.87,53.36 45.36,53.85 47.96,53.85 49.57,55.46 49.57,56.34 49.79,56.56 50.93,56.56 v6(51.36,56.99) ; 45.9,50.08 45.9,48.97 45.25,48.32 v3(44.07,48.32)
  S3 w0.064: v3(44.07,48.32) 43.09,47.34 43.09,47.32 v4(43.01,47.32) ; v4(19.94,28.48) v3(24.57,28.48)
  S6 w0.064: v1(43.21,47.54) 43.21,47.44 43.09,47.32 v4(43.01,47.32) 43.01,47.24 41.38,45.61 41.38,45.03 39.14,42.8 37.4,42.8 36.54,41.94 34.56,41.94 33.22,40.59 22.16,40.59 19.66,38.09 19.66,37.26 20.07,36.86 20.07,28.61 v4(19.94,28.48)
  BOTTOM w0.066: TP2617.1 51.5,59.18 50.8,58.48 50.8,57.55 v6(51.36,56.99) ; D26002.2 43.3,47.63 43.3,47.63 v1(43.21,47.54)
VPH_PWR: length 9.5
  TOP w0.15: PMIC1.D2 33.96,17.96 ; 32.9,18.76 v3(32.87,18.8)
  TOP w0.16: v3(36.14,16.26) 36.14,16.05 36.14,16.05 36.14,15.69 PMIC1.N7
  TOP w0.2: PMIC1.R25 PMIC1.P24 ; PMIC1.B14 PMIC1.A13 38.04,19.29 ; v3(39.27,17.2) 38.78,17.2 PMIC1.G17 ; PMIC1.Y18 39.28,13.74 39.8,13.74 PMIC1.W21 ; PMIC1.E3 PMIC1.D2 ; C1004.1 32.9,18.76 33.7,17.96 33.96,17.96
  G2 w0.2: v2(38.12,13.72) 38.41,13.43 38.92,13.43 38.94,13.41 v3(38.93,13.41)
  S3 w0.2: v3(36.14,16.26) 36.14,16.19 36.28,16.05 36.28,15.89 ; v3(35.77,15.41) 36.25,15.89 36.28,15.89 ; v3(39.27,17.2) 39.27,17.2 39.23,17.15 v4(39,17.15) ; v4(39.07,13.17) 39.07,13.28 38.94,13.41 38.94,13.41 v3(38.93,13.41) ; 36.28,15.89 v4(36.3,15.88)
  S6 w0.2: v5(38.96,13.44) 39.07,13.33 v4(39.07,13.17)
  BOTTOM w0.2: C901.1 v1(36.26,15.43)
  vias: v2(32.44,19.61) v2(32.66,18.85) v2(32.79,19.25) v2(37.82,20.4) v2(38.15,20.07) v2(38.56,20.19) v2(38.68,20.02) v2(46.02,13.84) v2(46.02,13.64) v2(46,13.41) v2(46,13) v2(46,12.8) v2(46,12.6) v2(46,12.22) v2(46,11.99) v2(46,11.76) v2(46.08,13.21) v2(46.1,12.4) v3(32.44,19.61) v3(32.66,18.85) v3(32.79,19.25) v3(37.82,20.4) v3(38.15,20.07) v3(38.56,20.19) v3(38.68,20.02) v3(46.02,13.84) v3(46.02,13.64) v3(46,13.41) v3(46,13) v3(46,12.8) v3(46,12.6) v3(46,12.22) v3(46,11.99) v3(46,11.76) v3(46.08,13.21) v3(46.1,12.4) v4(32.47,19.33) v4(32.69,18.57) v4(38.1,20.35) v4(38.91,20.19) v4(46.3,13.77) v4(46.3,13.39) v4(46.3,13) v4(46.31,12.6) v4(46.34,12.22) v4(46.3,11.84) v5(32.44,18.72) v5(32.4,18.52) v5(32.75,19.37) v5(32.72,19.18) v5(36.59,15.86) v5(36.56,15.66) v5(37.84,20.45) v5(37.84,20.23) v5(38.88,16.9) v5(39.13,16.91) v5(39.17,20.32) v5(39.17,20.09) v5(45.85,13.71) v5(45.87,13.44) v5(45.85,13.17) v5(45.87,12.9) v5(45.88,12.63) v5(45.91,12.36) v5(45.88,12.09) v5(45.91,11.82) v5(46.03,13.83) v5(46.01,13.6) v5(46.03,13.29) v5(46.01,13.06) v5(46.05,12.51) v5(46.05,11.97) v5(46.06,12.74) v5(46.06,12.2) v5(46.06,11.7)
VREF_LPDDR3: length 11.2
  TOP w0.066: PMIC1.M10 v3(36.85,15.7) ; C717.1 v3(36.38,9.95)
  S3 w0.203: v3(36.38,9.95) 36.38,9.89 36.2,9.7 36.2,9.74 36.17,9.74 36.17,9.73 v4(36.18,9.73) ; v3(36.85,15.7) 37.03,15.52 v4(37.08,15.52)
  S6 w0.203: v4(37.08,15.52) 37.08,15.42 36.88,15.22 36.88,14.24 37.3,13.82 37.44,13.82 38.78,12.48 38.79,12.48 39.67,11.6 39.67,10.42 39,9.75 36.25,9.75 36.2,9.7 36.2,9.74 36.17,9.74 36.17,9.73 v4(36.18,9.73)
VREF_MSM_1P25V: length 48.8
  TOP w0.127: PMIC1.N13 37.58,15.4 38,15.4 38.69,14.71 38.69,12.66 v3(38.9,12.45)
  S3 w0.127: v3(38.65,11.02) 38.65,12.2 v3(38.9,12.45)
  S3 w0.2: v3(26.17,33.67) 26.17,33.67 26.17,33.67 26.18,33.67 26.18,33.77 26.29,33.88 26.29,33.9 26.25,33.94 26.25,33.94 v4(26.23,33.94) ; v4(26.17,32.61) v3(26.17,32.88)
  S3 w0.203: v4(38.95,11.02) v3(38.65,11.02)
  S6 w0.15: v1(25.71,32.49) 25.14,31.92 v1(24.68,31.92) 22.43,31.92 22.1,31.59 22.1,15.95 27.6,10.45 38.38,10.45 v4(38.95,11.02)
  S6 w0.2: v1(25.71,32.49) 26.05,32.49 v4(26.17,32.61) 25.96,32.81 25.96,32.86 25.93,32.89 25.93,33.6 26.22,33.88 26.29,33.88 26.29,33.9 26.25,33.94 26.25,33.94 v4(26.23,33.94)
  BOTTOM w0.2: v1(24.68,31.92) C1703.1
  BOTTOM w0.203: v1(25.71,32.49) 25.71,32.16 25.47,31.92 C1703.1
VREF_TXDAC_1P25V: length 37.3
  S3 w0.2: v3(26.57,34.88) 26.57,35.04 v4(26.66,35.14)
  S3 w0.203: v3(30.71,15.66) 31.08,15.29 32.07,15.29 32.18,15.19 32.16,15.19 32.12,15.19 32.12,15.07 32.15,15.07 32.15,15.06 v4(32.14,15.06) ; v4(36.37,14.27) 36.37,14.45 v3(36.27,14.55)
  V5 w0.2: v4(32.14,15.06) 32.15,15.06 32.15,15.07 32.12,15.07 32.12,15.06 32,15.19 31.55,15.19 31.01,15.72 27.24,15.72 23.76,19.2 23.76,34.05 25.49,35.78 26.45,35.78 26.66,35.57 v4(26.66,35.14)
  V5 w0.203: v4(32.14,15.06) 32.14,14.95 32.5,14.59 32.83,14.59 33.16,14.92 33.52,14.92 34.75,13.69 35.7,13.69 36.22,14.21 36.37,14.21 v4(36.37,14.27)
  S6 w0.2: v1(26.94,35.13) 26.67,35.13 v4(26.66,35.14)
VREG_L1A_0P848V: length 16.1
  TOP w0.1: v3(29.37,31.28) 28.99,31.66 v3(28.95,31.66)
  TOP w0.2: 31.37,34.88 v4(31.37,34.48) v3(31.37,34.08) v2(31.37,33.68) v2(31.37,33.28) v2(31.37,32.88) v3(31.37,32.48) v3(30.57,32.48) ; v3(32.57,32.48) v3(32.57,33.28) v3(32.57,34.48) v3(32.57,35.28) v3(32.57,36.08) v3(32.57,36.88) ; v3(28.17,34.48) v3(27.77,34.48) ; v3(26.97,32.48) v3(26.97,32.08) ; v3(28.57,36.88) v2(28.57,36.48) v3(28.57,36.08) v2(28.57,35.68) v3(28.57,35.28) v2(28.57,34.88) ; 30.17,30.88 30.17,30.9 29.72,30.9 29.37,31.26 v3(29.37,31.28) ; v3(31.37,36.48) v4(31.37,36.08) v4(31.37,35.28)
  S3 w0.2: v4(29.84,33.16) 29.77,33.09 v3(29.77,32.88) ; v4(29.43,31) 29.43,31.22 v3(29.37,31.28) ; v4(28.67,31.67) 28.67,31.67 28.67,31.68 28.97,31.68 28.97,31.66 28.95,31.66 v3(28.95,31.66)
  S6 w0.2: v1(32.7,32.71) 32.79,32.81 33.06,32.81 33.1,32.84 v1(33.1,32.86) ; v1(26.75,32.46) 26.97,32.68 v4(26.97,32.78) ; v5(29.71,32.84) 29.71,33.03 v4(29.84,33.16) ; v1(31.56,33) 31.55,33 31.55,33.02 31.54,33.03 31.52,33.03 v4(31.36,33.19)
  BOTTOM w0.203: C1738.1 32.85,34.83 v1(32.84,34.82) ; C1727.1 32.59,31.8 v1(32.63,31.76) ; v1(32.76,32.2) 32.66,32.31 C1903.1
  vias: v1(28.37,36.75) v1(28.4,36.02) v1(28.44,35.51) v1(28.63,37.01) v1(28.56,36.15) v1(28.79,35.16) v1(28.76,34.67) v1(29.01,31.41) v1(29.52,31.44) v1(29.6,31.25) v1(31.07,36.12) v1(31.21,36.55) v1(31.29,34) v1(31.29,33.46) v1(31.35,35.01) v1(31.75,34.48) v1(32.63,35.48) v1(32.78,36.38) v2(31.38,35.73) v2(31.39,34.89) v2(32.56,31.73) v2(35.03,21.44) v2(35.02,21.22) v2(35.02,21) v2(35.02,20.78) v2(35.02,20.55) v2(35.02,20.33) v2(35.02,20.11) v3(31.38,35.73) v3(31.39,34.89) v3(32.56,31.73) v3(35.03,21.44) v3(35.02,21.22) v3(35.02,21) v3(35.02,20.78) v3(35.02,20.55) v3(35.02,20.33) v3(35.02,20.11) v4(28.42,34.66) v4(28.6,36.58) v4(28.57,35.78) v4(28.57,34.98) v4(31.38,33.73) v4(32.55,32.03) v4(32.58,36.56) v4(32.57,35.77) v4(32.61,34.98) v4(32.62,33.01) v4(35.31,21.35) v4(35.31,20.97) v4(35.31,20.59) v4(35.31,20.22) v5(28.37,36.75) v5(28.4,36.02) v5(28.44,35.51) v5(28.63,37.01) v5(28.56,36.15) v5(28.79,35.16) v5(28.76,34.67) v5(29.01,31.41) v5(29.52,31.44) v5(29.6,31.25) v5(31.07,36.12) v5(31.21,36.55) v5(31.29,34) v5(31.29,33.46) v5(31.35,35.01) v5(31.75,34.48) v5(32.63,35.48) v5(32.78,36.38) v5(35.6,21.5) v5(35.6,21.27) v5(35.6,21.05) v5(35.6,20.83) v5(35.6,20.61) v5(35.6,20.38) v5(35.6,20.16)
VREG_L2A_1P128V: length 13.4
  TOP w0.084: DRAM1.R1 37.1,32.01 37.09,32 v3(37.07,32)
  TOP w0.2: DRAM1.K10 v3(44.66,34.96) ; v3(38.24,18.36) 38.24,18.36 v3(38.41,18.53)
  S3 w0.127: v4(38.04,35.4) 37.96,35.32 v3(37.46,35.32) ; v4(43.27,38.05) 43.25,38.05 v3(43.06,37.86) ; v4(40.46,38.05) 40.47,38.05 v3(40.66,37.86) ; v3(40.66,36.56) 40.66,36.51 v4(40.49,36.34) ; v3(39.06,33.34) 38.69,33.34 v4(38.66,33.3) ; v3(37.07,32) 36.69,32 v4(36.58,32.11) ; v3(42.97,31.89) 42.67,31.89 v4(42.62,31.84) ; v4(43.35,36.56) 43.07,36.56 v3(43.06,36.56) ; v4(46.55,33.31) v3(46.26,33.31) ; v4(37.99,31.35) 38.19,31.35 v3(38.26,31.28) ; v4(37.75,33.3) 37.72,33.34 v3(37.46,33.34) ; v3(39.06,35.32) 38.85,35.32 38.84,35.34 38.54,35.34 v4(38.45,35.42) ; v4(37.12,36.77) 37.12,36.75 v3(37.31,36.56) ; v4(38.55,37.22) 38.53,37.2 v3(38.27,37.2)
  S3 w0.2: v3(40.66,32.01) v4(40.46,31.81) ; v3(46.26,36.56) v4(46.55,36.56) ; v3(39.86,27.46) 39.86,27.19 v4(39.85,27.17) ; v4(33.45,31.15) 33.45,31.14 33.37,31.06 v3(33.37,30.88) ; v3(43.06,30.71) v4(42.72,30.71) ; v4(33.47,31.8) 33.4,31.8 33.4,31.79 33.49,31.79 33.37,31.91 v3(33.37,32.08) ; v4(33.05,35.27) 33.05,35.27 33.05,35.27 33.06,35.27 33.06,35.24 33.06,35.26 33.1,35.26 33.1,35.23 33.15,35.28 v3(33.37,35.28) ; v3(33.43,36.49) 33.37,36.49 v4(33.37,36.76) ; v3(46.26,35.26) 46.55,35.26 v4(46.55,35.26) ; v3(40.66,30.71) v4(40.39,30.71) ; v3(44.66,34.96) 44.92,34.96 44.93,34.98 v4(44.94,34.98) ; v3(46.26,32.01) v4(46.55,32.01) ; v3(43.86,27.46) v4(43.86,27.17)
  S3 w0.203: v3(44.66,33.31) 44.86,33.51 v4(44.86,33.51) ; v3(33.39,33.28) 33.39,33.55 v4(33.37,33.57)
  S6 w0.2: v4(46.55,35.26) 46.53,35.26 46.47,35.19 v1(46.47,34.97) ; v1(37.12,36.4) 37.12,36.77 v4(37.12,36.77) ; v1(40.01,27.53) 40.01,27.34 v4(39.85,27.17)
  S6 w0.3: 46.55,32.01 46.49,31.95 v1(46.21,31.95) ; v1(46.18,33.19) 46.43,33.19 46.55,33.31 ; 36.62,32.16 36.61,32.17 v1(36.61,32.55)
  BOTTOM w0.203: v1(34.4,34.25) 34.51,34.36 C2210.1
  vias: v1(33.84,36.91) v1(34.29,31.25) v2(39.86,41.12) v2(41.15,22.53) v2(41.15,21.52) v2(41.43,22.18) v2(41.43,21.17) v2(43.86,41.11) v3(39.86,41.12) v3(41.15,22.53) v3(41.15,21.52) v3(41.43,22.18) v3(41.43,21.17) v3(43.86,41.11) v4(46.48,34.66) v4(46.55,33.68) v5(33.84,36.91) v5(34.29,31.25)
VREG_L3A_0P6V: length 20.4
  TOP w0.125: v3(33.37,32.88) v2(32.97,33.28) ; v2(32.97,35.28) v3(33.37,35.68)
  TOP w0.2: 32.97,34.88 v2(32.97,35.28)
  TOP w0.203: 32.97,36.86 SOC1.G9 ; 32.97,36.86 v3(32.97,36.86) ; 32.97,36.86 32.97,36.55 v3(32.95,36.55) SOC1.G10 ; v2(32.97,33.28) v3(32.97,33.68) ; 32.97,31.68 v3(32.97,32.08)
  G2 w0.203: v2(32.97,33.28) SOC1.G18 33.15,33.1 33.15,33.05
  S3 w0.127: 42.85,27.92 v4(42.8,27.92) ; v4(40.97,29.34) 40.93,29.34 40.87,29.41 v3(40.66,29.41) ; v3(40.66,28.11) 40.79,28.23 v4(40.93,28.23) ; v3(40.66,40.46) v4(40.86,40.65) ; v3(43.06,28.11) 43.04,28.11 ; v3(44.66,30.71) 44.51,30.55 v4(44.43,30.55) ; v3(43.06,29.41) 42.87,29.22 v4(42.84,29.22)
  S3 w0.2: v3(44.66,28.11) v4(44.97,28.11) ; v3(37.46,29.41) v4(37.46,29.69) ; v3(39.06,28.11) 39.06,28.1 39.04,28.1 38.95,28.02 38.88,28.02 v4(38.82,27.96) ; v3(40.66,39.16) 40.65,39.16 v4(40.46,39.35) ; v3(32.97,32.08) 32.97,31.7 v3(32.95,31.7) 32.95,31.67 32.7,31.42 v4(32.7,31.35) ; v3(44.66,40.46) 44.65,40.46 v4(44.46,40.65) ; v4(33.08,35.72) 33.08,35.72 33.08,35.72 33.08,35.71 33.08,35.68 33.11,35.68 v3(33.37,35.68) ; v4(39.28,38.12) 39.09,37.93 v3(39.07,37.93) ; v3(43.06,40.46) 43.08,40.46 v4(43.27,40.65) ; v3(43.06,39.16) 42.86,39.16 42.8,39.22 v4(42.8,39.22) ; v4(39.27,40.65) 39.07,40.46 v3(39.06,40.46) ; v4(39.35,30.71) 39.35,30.71 v3(39.06,30.71) ; v4(46.56,29.41) 46.56,29.41 v3(46.26,29.41) ; v3(46.26,39.16) v4(46.55,39.16) ; v4(37.66,39.36) 37.46,39.17 v3(37.46,39.16) ; v4(44.92,37.71) 44.78,37.86 v3(44.68,37.86) ; v3(40.66,40.46) v4(40.86,40.65)
  S6 w0.2: v1(44.78,30.39) 44.59,30.39 v4(44.43,30.55) ; v1(37.63,29.41) 37.63,29.53 v4(37.46,29.69) ; v1(43.03,28.1) 42.85,27.92 v4(42.8,27.92) ; v4(44.97,28.11) 45.25,28.11 45.26,28.1 v1(45.51,28.1) ; v1(38.68,27.66) 38.68,27.82 v4(38.82,27.96) ; v4(33.08,35.72) 33.08,35.72 33.08,35.72 33.08,35.71 33.08,35.68 33.35,35.68 v1(33.4,35.64) ; v1(41.16,41.11) v4(41.89,41.11) 42.56,41.78 v1(42.56,41.95) ; v1(37.75,39.07) 37.66,39.17 v4(37.66,39.36) ; v1(32.91,31.54) 32.72,31.35 v4(32.7,31.35) ; v1(40.75,39.2) 40.6,39.35 v4(40.46,39.35) ; v1(33.32,37.2) 33.06,37.2 v4(32.99,37.13) ; v1(39.28,38.47) v4(39.28,38.12)
  S6 w0.203: v4(32.93,33.41) 32.93,33.75 v1(33.05,33.87)
  G7 w0.15: 33.06,33.86 33.04,33.88 33.04,33.87 33.05,33.87 33.05,33.87 v1(33.05,33.87)
  BOTTOM w0.125: C1925.1 33.09,31.35 v1(32.91,31.54)
  BOTTOM w0.2: C1936.1 33.37,35.8 33.6,36.04 34.11,36.04 34.39,35.76 R1401.1
  BOTTOM w0.203: C1938.1 33.12,33.84 33.41,33.55 C2203.1
  BOTTOM w0.254: C2215.1 45.54,28.13 v1(45.51,28.1)
  vias: v2(32.97,34.87) v2(37.28,17.96) v2(37.83,22.18) v2(37.87,23.94) v2(38.16,23.72) v2(38.15,21.99) v3(33.19,33.04) v3(37.28,17.96) v3(37.83,22.18) v3(37.87,23.94) v3(38.16,23.72) v3(38.15,21.99) v4(42.38,28.62) v4(42.54,28.97) v4(42.51,28.17)
